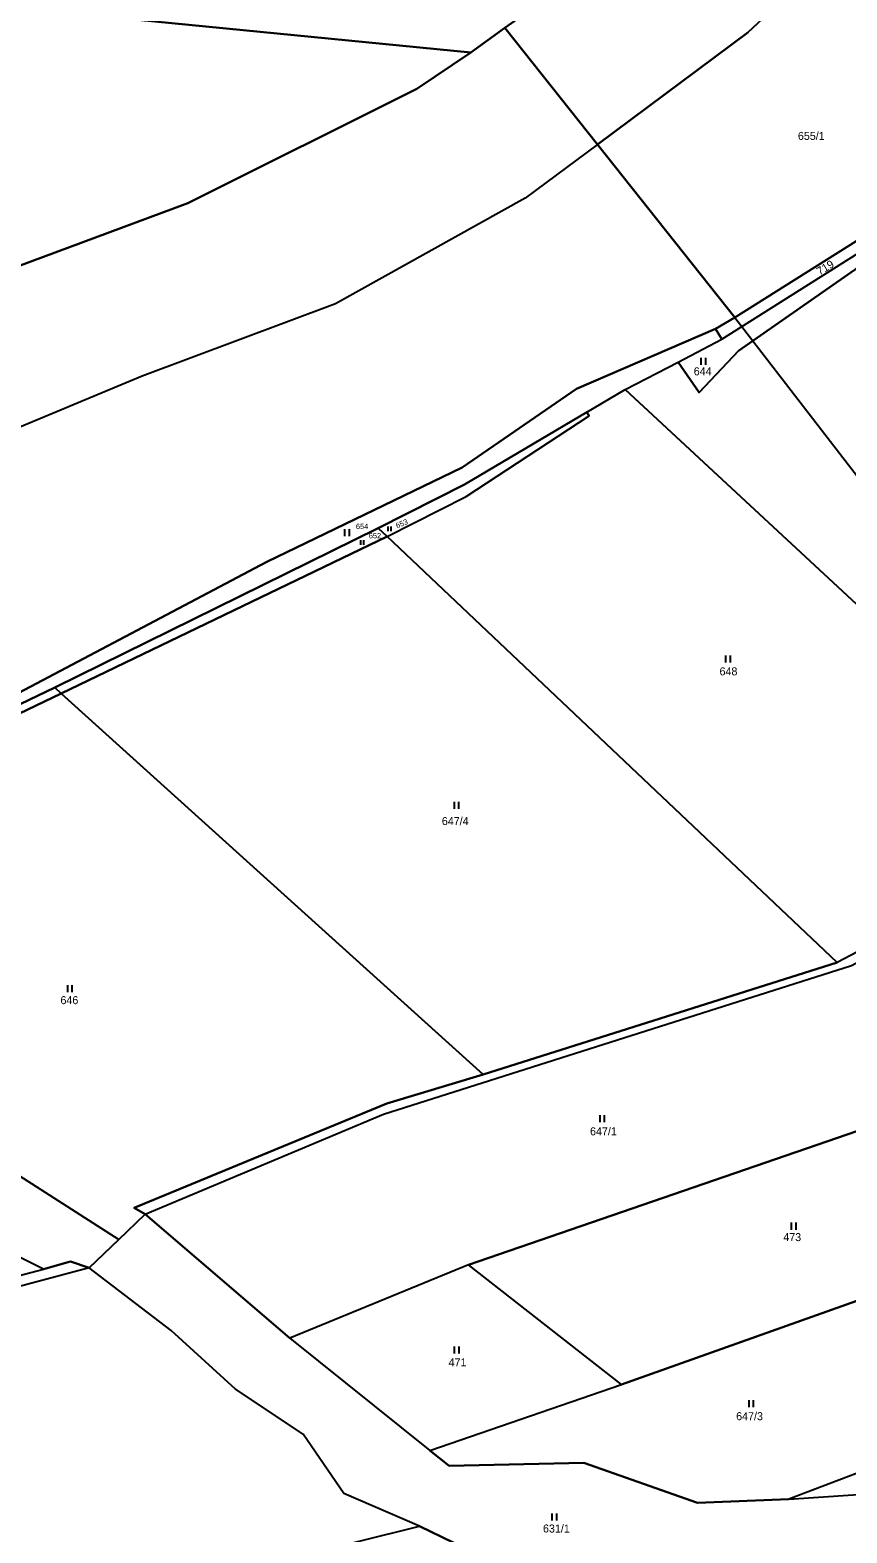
# Model space of a CAD drawing. Extents: x -590606 to -587796, y -1065936 to -1062515.
# Drawn here: x -589814.6 to -589641.2, y -1065080 to -1064760.8 of the extents above; entities that cross this region are included whole.
import ezdxf

# ---------------------------------------------------------------- set-up
doc = ezdxf.new("R2010")
doc.units = 0
for name, color, linetype in [('Parcela nároku', 7, 'Continuous'), ('Vrstva 30', 7, 'Continuous'), ('Územní plán', 7, 'Continuous')]:
    doc.layers.add(name, color=color, linetype=linetype)

msp = doc.modelspace()

# ---------------------------------------------------------------- linework, layer by layer
at = {"layer": 'Parcela nároku'}
for points in [[(-589680.26, -1064689.83), (-589650.2, -1064705.57), (-589660.64, -1064716.31), (-589690.55, -1064743.96), (-589713.8, -1064760.35), (-589721.04, -1064765.62), (-589866.87, -1064751.2), (-589844.17, -1064740.14), (-589796.41, -1064719.77), (-589777.67, -1064709.79), (-589778.73, -1064718.01), (-589723.58, -1064702.36), (-589724.05, -1064691.59)], [(-589627.72, -1064729.04), (-589660.64, -1064716.31), (-589690.55, -1064743.96), (-589713.8, -1064760.35), (-589694.16, -1064785.11), (-589662.24, -1064761.36)], [(-589605.54, -1064732.57), (-589618.13, -1064717.98), (-589627.72, -1064729.04), (-589662.24, -1064761.36), (-589694.16, -1064785.11), (-589664.99, -1064821.89), (-589630.44, -1064800.11), (-589618.14, -1064787.77), (-589635.08, -1064761.95), (-589628.69, -1064755.59), (-589628.92, -1064755.19), (-589627.45, -1064754.35)], [(-589879.87, -1064753.99), (-589868.03, -1064748.13), (-589866.87, -1064751.2), (-589721.04, -1064765.62), (-589732.48, -1064773.33), (-589781.14, -1064797.6), (-589848.05, -1064822.46), (-589965.99, -1064862.62), (-590008.01, -1064872.65), (-590021.45, -1064817.05), (-590021.33, -1064814.7), (-589976.81, -1064797.92), (-589940.65, -1064780.54)], [(-589848.05, -1064822.46), (-589781.14, -1064797.6), (-589732.48, -1064773.33), (-589721.04, -1064765.62), (-589713.8, -1064760.35), (-589694.16, -1064785.11), (-589709.51, -1064796.54), (-589749.8, -1064818.94), (-589790.83, -1064834.34), (-589885.81, -1064873.92), (-589959.21, -1064893.84), (-589981.68, -1064896.99), (-590005.25, -1064904.42), (-590008.77, -1064887.64), (-590008.01, -1064872.65), (-589965.99, -1064862.62)], [(-589593.02, -1064762.59), (-589618.14, -1064787.77), (-589630.44, -1064800.11), (-589664.99, -1064821.89), (-589669.05, -1064824.3), (-589667.75, -1064826.48), (-589630.17, -1064802.74), (-589591.88, -1064765.77)], [(-589749.8, -1064818.94), (-589790.83, -1064834.34), (-589885.81, -1064873.92), (-589959.21, -1064893.84), (-589981.68, -1064896.99), (-590005.25, -1064904.42), (-590004.21, -1064948.26), (-589983.27, -1064948.69), (-589877.03, -1064922.22), (-589830.91, -1064908.85), (-589764.34, -1064873.79), (-589722.86, -1064853.73), (-589698.59, -1064837.06), (-589669.05, -1064824.3), (-589664.99, -1064821.89), (-589694.16, -1064785.11), (-589709.51, -1064796.54)], [(-589672.56, -1064837.8), (-589664.19, -1064828.97), (-589628.67, -1064804.2), (-589550.69, -1064880.06), (-589595.93, -1064922.82), (-589688.26, -1064837.19), (-589677.04, -1064831.33)], [(-589630.17, -1064802.74), (-589628.67, -1064804.2), (-589664.19, -1064828.97), (-589672.56, -1064837.8), (-589677.04, -1064831.33), (-589667.75, -1064826.48)], [(-589830.91, -1064908.85), (-589877.03, -1064922.22), (-589983.27, -1064948.69), (-590004.21, -1064948.26), (-590004.15, -1064950.82), (-589982.95, -1064950.18), (-589939.73, -1064939.92), (-589923.24, -1064936.02), (-589827.57, -1064909.16), (-589809.38, -1064900.48), (-589740.68, -1064866.6), (-589722.41, -1064857.38), (-589696.42, -1064842.01), (-589688.26, -1064837.19), (-589677.04, -1064831.33), (-589667.75, -1064826.48), (-589669.05, -1064824.3), (-589698.59, -1064837.06), (-589722.86, -1064853.73), (-589764.34, -1064873.79)], [(-589738.8, -1064868.37), (-589722.06, -1064859.86), (-589695.94, -1064842.79), (-589696.42, -1064842.01), (-589688.26, -1064837.19), (-589595.93, -1064922.82), (-589621.92, -1064947.69), (-589643.25, -1064958.89)], [(-589695.94, -1064842.79), (-589696.42, -1064842.01), (-589722.41, -1064857.38), (-589740.68, -1064866.6), (-589738.8, -1064868.37), (-589722.06, -1064859.86)], [(-589738.8, -1064868.37), (-589740.68, -1064866.6), (-589809.38, -1064900.48), (-589808.02, -1064901.71)], [(-589643.25, -1064958.89), (-589738.8, -1064868.37), (-589808.02, -1064901.71), (-589718.4, -1064982.65)], [(-589643.25, -1064958.89), (-589718.4, -1064982.65), (-589738.86, -1064988.82), (-589792.56, -1065010.99), (-589790.16, -1065012.34), (-589739.56, -1064991.1), (-589640.21, -1064959.48), (-589620.7, -1064948.96), (-589616.14, -1064944.82), (-589588.94, -1064920.46), (-589549.47, -1064883.45), (-589550.69, -1064880.06), (-589595.93, -1064922.82), (-589621.92, -1064947.69)], [(-589809.38, -1064900.48), (-589827.57, -1064909.16), (-589923.24, -1064936.02), (-589921.46, -1064937.16), (-589871.6, -1064924.56), (-589827.68, -1064911.18), (-589808.02, -1064901.71)], [(-589718.4, -1064982.65), (-589808.02, -1064901.71), (-589827.68, -1064911.18), (-589871.6, -1064924.56), (-589921.46, -1064937.16), (-589843.52, -1064987), (-589827.23, -1064997.59), (-589795.76, -1065017.7), (-589790.16, -1065012.34), (-589792.56, -1065010.99), (-589738.86, -1064988.82)], [(-589739.56, -1064991.1), (-589640.21, -1064959.48), (-589620.7, -1064948.96), (-589616.14, -1064944.82), (-589592.46, -1064971.67), (-589606.65, -1064981.94), (-589625.91, -1064990.19), (-589721.56, -1065023.05), (-589759.46, -1065038.64), (-589790.16, -1065012.34)], [(-589893.12, -1064991.88), (-589878.15, -1064990.41), (-589836.22, -1064994.59), (-589827.23, -1064997.59), (-589795.76, -1065017.7), (-589802.07, -1065023.73), (-589806.02, -1065022.39), (-589811.77, -1065023.97), (-589849.91, -1065004.87), (-589883.73, -1065003.75), (-589904.18, -1065013.33), (-589933.24, -1065004.69), (-589933.01, -1064998.63), (-589976.96, -1064978.12), (-590010.18, -1064970.13), (-590009.89, -1064958.56), (-590004.13, -1064951.75), (-590004.15, -1064950.82), (-589982.95, -1064950.18), (-589966.86, -1064965.11), (-589917.96, -1064995.7), (-589907.33, -1065000.76)], [(-589625.91, -1064990.19), (-589606.65, -1064981.94), (-589586.97, -1065009.02), (-589620.06, -1065023.62), (-589639.08, -1065030.72), (-589689.01, -1065048.5), (-589721.56, -1065023.05)], [(-589811.77, -1065023.97), (-589849.91, -1065004.87), (-589883.73, -1065003.75), (-589904.18, -1065013.33), (-589933.24, -1065004.69), (-589933.87, -1065030.44), (-589934.45, -1065056.25)], [(-589540.15, -1065017.98), (-589573.43, -1065039.74), (-589626.65, -1065062.62), (-589653.49, -1065072.84), (-589619.91, -1065070.61), (-589610.04, -1065071.9), (-589592.92, -1065066.04), (-589590.3, -1065065.14), (-589568.75, -1065053.81), (-589558.18, -1065064.74), (-589543.69, -1065062.64), (-589544.64, -1065069.18), (-589541.38, -1065066.73)], [(-589731.97, -1065078.6), (-589747.98, -1065071.62), (-589756.67, -1065059.05), (-589771, -1065049.48), (-589784.67, -1065037.04), (-589802.07, -1065023.73), (-589923.15, -1065056.06), (-590043.11, -1065087.66), (-590064.6, -1065165.95), (-590006.04, -1065151.63), (-589920.53, -1065125.45)], [(-589806.02, -1065022.39), (-589802.07, -1065023.73), (-589923.15, -1065056.06), (-590043.11, -1065087.66), (-590042.18, -1065084.25), (-589934.45, -1065056.25), (-589811.77, -1065023.97)], [(-589689.01, -1065048.5), (-589721.56, -1065023.05), (-589759.46, -1065038.64), (-589729.74, -1065062.5)], [(-589639.08, -1065030.72), (-589626.65, -1065062.62), (-589653.49, -1065072.84), (-589672.93, -1065073.61), (-589697.05, -1065065.15), (-589725.64, -1065065.8), (-589729.74, -1065062.5), (-589689.01, -1065048.5)], [(-590081.71, -1065215.34), (-590064.6, -1065165.95), (-590006.04, -1065151.63), (-589920.53, -1065125.45), (-589731.97, -1065078.6), (-589717.32, -1065085.65), (-589705.52, -1065107.06), (-589754.85, -1065114.01), (-589901.4, -1065149.05), (-589979.61, -1065173.58)]]:
    msp.add_lwpolyline(points, close=True, dxfattribs=at)
msp.add_lwpolyline([(-589717.32, -1065085.65), (-589731.97, -1065078.6), (-589747.98, -1065071.62), (-589756.67, -1065059.05), (-589771, -1065049.48), (-589784.67, -1065037.04), (-589802.07, -1065023.73), (-589795.76, -1065017.7), (-589790.16, -1065012.34), (-589759.46, -1065038.64), (-589729.74, -1065062.5), (-589725.64, -1065065.8), (-589697.05, -1065065.15), (-589672.93, -1065073.61), (-589653.49, -1065072.84), (-589619.91, -1065070.61), (-589610.04, -1065071.9), (-589592.92, -1065066.04), (-589590.05, -1065069.91), (-589620.93, -1065074.85), (-589621.05, -1065080.6)], dxfattribs=at)
at = {"layer": 'Vrstva 30'}
for p, q in [((-589672.16, -1064830.44), (-589672.16, -1064831.94)), ((-589671.14, -1064831.94), (-589671.14, -1064830.44)), ((-589747.83, -1064866.85), (-589747.83, -1064868.35)), ((-589746.81, -1064868.35), (-589746.81, -1064866.85)), ((-589738.63, -1064866.27), (-589738.63, -1064867.27)), ((-589737.94, -1064867.27), (-589737.94, -1064866.27)), ((-589744.48, -1064869.16), (-589744.48, -1064870.16)), ((-589743.79, -1064870.16), (-589743.79, -1064869.16)), ((-589666.92, -1064893.66), (-589666.92, -1064895.16)), ((-589665.9, -1064895.16), (-589665.9, -1064893.66)), ((-589724.59, -1064924.76), (-589724.59, -1064926.26)), ((-589723.57, -1064926.26), (-589723.57, -1064924.76)), ((-589806.68, -1064963.65), (-589806.68, -1064965.15)), ((-589805.66, -1064965.15), (-589805.66, -1064963.65)), ((-589693.65, -1064991.29), (-589693.65, -1064992.79)), ((-589692.62, -1064992.79), (-589692.62, -1064991.29)), ((-589653.01, -1065014.12), (-589653.01, -1065015.62)), ((-589651.98, -1065015.62), (-589651.98, -1065014.12)), ((-589724.54, -1065040.4), (-589724.54, -1065041.9)), ((-589723.52, -1065041.9), (-589723.52, -1065040.4)), ((-589662.01, -1065051.79), (-589662.01, -1065053.29)), ((-589660.98, -1065053.29), (-589660.98, -1065051.79)), ((-589703.8, -1065075.86), (-589703.8, -1065077.36)), ((-589702.78, -1065077.36), (-589702.78, -1065075.86))]:
    msp.add_line(p, q, dxfattribs=at)
at = {"layer": 'Územní plán'}
msp.add_line((-589664.99, -1064821.89), (-589588.94, -1064920.46), dxfattribs=at)
msp.add_lwpolyline([(-589664.99, -1064821.89), (-589694.16, -1064785.11), (-589713.8, -1064760.35), (-589690.55, -1064743.96), (-589660.64, -1064716.31)], dxfattribs=at)

# ---------------------------------------------------------------- texts
at = {"layer": 'Parcela nároku'}
for s, height, p in [('655/1', 1.7, (-589651.58, -1064784.16)), ('644', 1.7, (-589673.7, -1064834.15)), ('654', 1.14, (-589745.44, -1064866.81)), ('652', 1.14, (-589742.7, -1064868.78)), ('648', 1.7, (-589668.22, -1064897.88)), ('647/4', 1.7, (-589727.19, -1064929.68)), ('646', 1.7, (-589808.18, -1064967.71)), ('647/1', 1.7, (-589695.72, -1064995.57)), ('473', 1.7, (-589654.68, -1065018.04)), ('471', 1.7, (-589725.76, -1065044.64)), ('647/3', 1.7, (-589664.69, -1065056.07)), ('631/1', 1.7, (-589705.71, -1065079.93))]:
    msp.add_text(s, height=height, dxfattribs=at).set_placement(p)
for s, height, rotation, p in [('719', 1.7, 31.1643, (-589646.96, -1064812.98)), ('653', 1.14, 22.8918, (-589736.7, -1064866.69))]:
    msp.add_text(s, height=height, rotation=rotation, dxfattribs=at).set_placement(p)

doc.saveas('drawing.dxf')
